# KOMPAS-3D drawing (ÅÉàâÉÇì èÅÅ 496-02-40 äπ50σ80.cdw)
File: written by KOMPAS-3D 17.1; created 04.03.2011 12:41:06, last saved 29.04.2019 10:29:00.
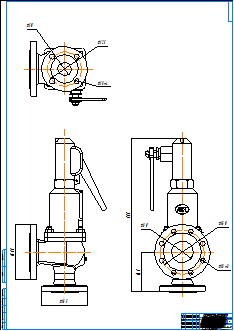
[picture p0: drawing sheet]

Sheet 1: A0, portrait

Title block, sheet 1: name: ПРЕГРАН КПП 496-02-40 / Ду50х80; material: Внимание! Данный продукт является объектом авторского права ООО «Торговый Дом АДЛ». / Запрещается изменение, копирование, распространение / (в том числе путем копирования на другие сайты и ресурсы в Интернете) / или любое иное использование информации и объектов без предварительного / согласия правообладателя (ООО «Торговый Дом АДЛ»).; scale: 1:1; sheets: 1; organisation: ООО "Торговый дом АДЛ"; sheet format: A0; stored path: C:\Users\tra\Desktop\2д чертежи\Предохранительные клапаны ПРЕГРАН\ПРЕГРАН 496\ПРЕГРАН КПП 496-02-40\KOMPAS 2D\ПРЕГРАН КПП 496-02-40 Ду50х80.cdw

Views: Спереди 1, Проекционный вид 2, Проекционный вид 3
Dimensions and other numbers on the sheet: 200; 165; 145; 555; 160; 18; 80; 125; 50; 1:1; 1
